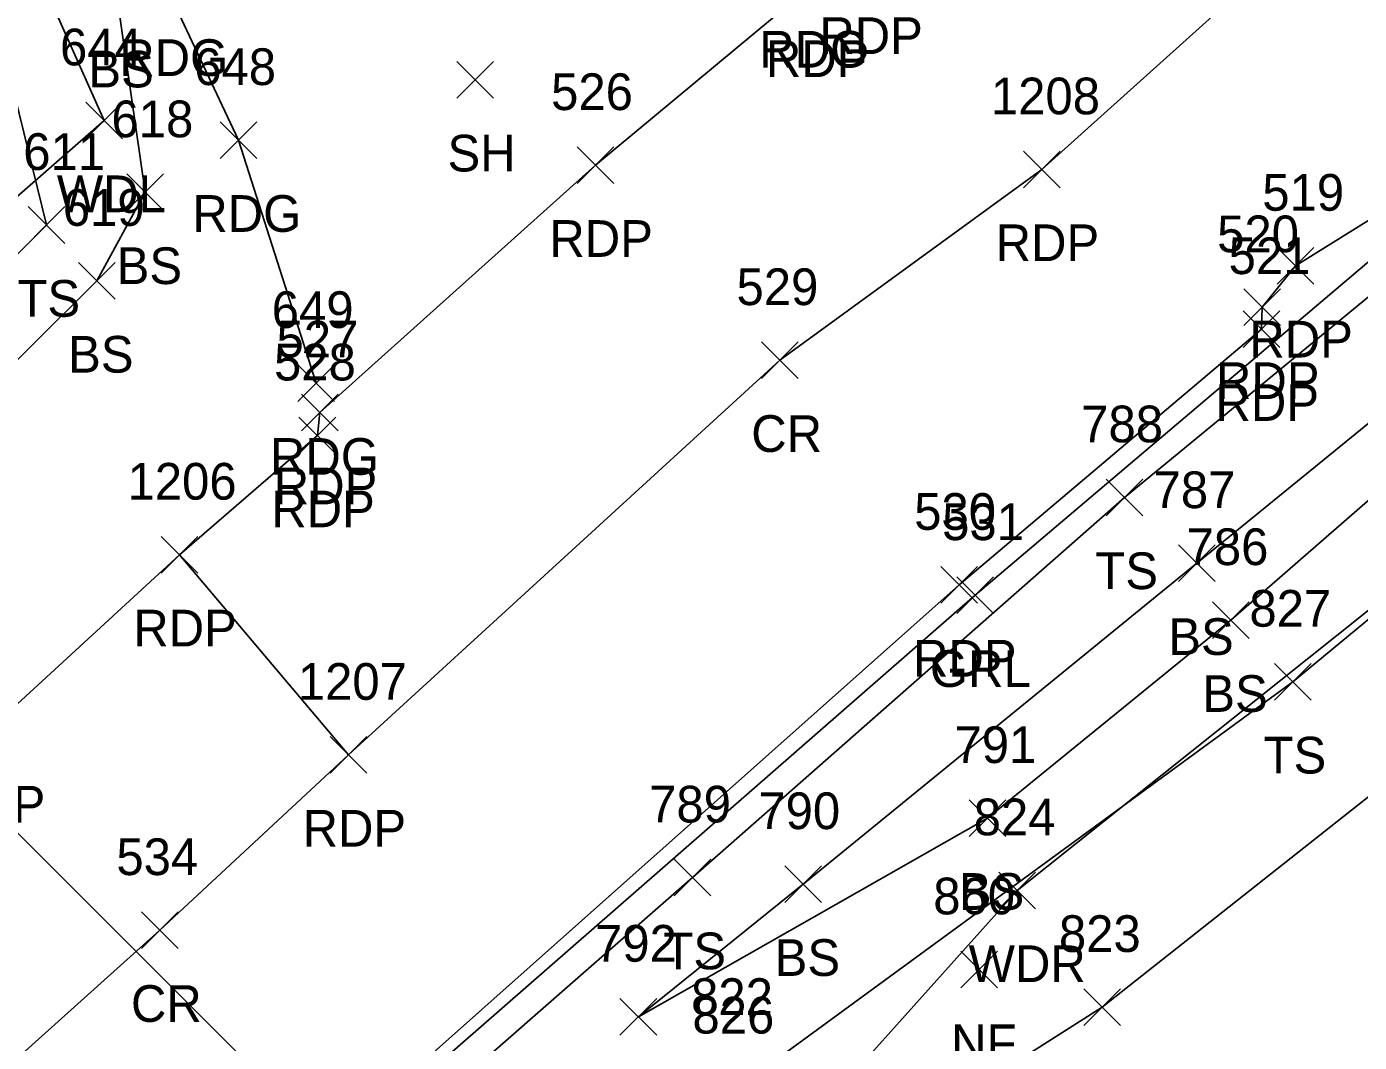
# Model space of a CAD drawing. Extents: x 1528286 to 1556263, y 492387 to 508952.
# Drawn here: x 1528468.6 to 1528541.2, y 492640.2 to 492695.5 of the extents above; entities that cross this region are included whole.
import ezdxf

# ---------------------------------------------------------------- set-up
doc = ezdxf.new("R2010")
doc.units = 0
for name, color, linetype in [('DCP', 7, 'Continuous'), ('L_A', 7, 'Continuous'), ('L_I', 7, 'Continuous'), ('L_TIC', 7, 'Continuous'), ('LAWA', 7, 'Continuous'), ('LELB', 7, 'Continuous'), ('P_A', 7, 'Continuous'), ('P_I', 7, 'Continuous'), ('P_TIC', 7, 'Continuous'), ('PET', 7, 'Continuous'), ('PEU', 7, 'Continuous'), ('PRC', 7, 'Continuous'), ('R_A', 7, 'Continuous'), ('R_I', 7, 'Continuous'), ('R_TIC', 7, 'Continuous'), ('RGR', 7, 'Continuous')]:
    doc.layers.add(name, color=color, linetype=linetype)

msp = doc.modelspace()

# ---------------------------------------------------------------- linework, layer by layer
at = {"layer": 'DCP'}
msp.add_line((1528459.882, 492659.784), (1528492.296, 492627.438), dxfattribs=at)
at = {"layer": 'L_TIC'}
for points in [[(1528492.036, 492691.653), (1528494.036, 492693.653)], [(1528494.036, 492691.653), (1528492.036, 492693.653)], [(1528492.036, 492691.653), (1528494.036, 492693.653)], [(1528494.036, 492691.653), (1528492.036, 492693.653)], [(1528471.803, 492689.435), (1528473.803, 492691.435)], [(1528473.803, 492689.435), (1528471.803, 492691.435)], [(1528471.803, 492689.435), (1528473.803, 492691.435)], [(1528473.803, 492689.435), (1528471.803, 492691.435)], [(1528474.042, 492685.518), (1528476.042, 492687.518)], [(1528476.042, 492685.518), (1528474.042, 492687.518)], [(1528474.042, 492685.518), (1528476.042, 492687.518)], [(1528476.042, 492685.518), (1528474.042, 492687.518)], [(1528468.663, 492683.737), (1528470.663, 492685.737)], [(1528470.663, 492683.737), (1528468.663, 492685.737)], [(1528468.663, 492683.737), (1528470.663, 492685.737)], [(1528470.663, 492683.737), (1528468.663, 492685.737)], [(1528471.395, 492680.69), (1528473.395, 492682.69)], [(1528473.395, 492680.69), (1528471.395, 492682.69)], [(1528471.395, 492680.69), (1528473.395, 492682.69)], [(1528473.395, 492680.69), (1528471.395, 492682.69)], [(1528527.44, 492668.894), (1528529.44, 492670.894)], [(1528529.44, 492668.894), (1528527.44, 492670.894)], [(1528527.44, 492668.894), (1528529.44, 492670.894)], [(1528529.44, 492668.894), (1528527.44, 492670.894)], [(1528531.387, 492665.306), (1528533.387, 492667.306)], [(1528533.387, 492665.306), (1528531.387, 492667.306)], [(1528531.387, 492665.306), (1528533.387, 492667.306)], [(1528533.387, 492665.306), (1528531.387, 492667.306)], [(1528533.242, 492662.203), (1528535.242, 492664.203)], [(1528535.242, 492662.203), (1528533.242, 492664.203)], [(1528533.242, 492662.203), (1528535.242, 492664.203)], [(1528535.242, 492662.203), (1528533.242, 492664.203)], [(1528536.612, 492658.846), (1528538.612, 492660.846)], [(1528538.612, 492658.846), (1528536.612, 492660.846)], [(1528536.612, 492658.846), (1528538.612, 492660.846)], [(1528538.612, 492658.846), (1528536.612, 492660.846)], [(1528519.965, 492651.416), (1528521.965, 492653.416)], [(1528521.965, 492651.416), (1528519.965, 492653.416)], [(1528519.965, 492651.416), (1528521.965, 492653.416)], [(1528521.965, 492651.416), (1528519.965, 492653.416)], [(1528503.886, 492648.176), (1528505.886, 492650.176)], [(1528505.886, 492648.176), (1528503.886, 492650.176)], [(1528503.886, 492648.176), (1528505.886, 492650.176)], [(1528505.886, 492648.176), (1528503.886, 492650.176)], [(1528509.922, 492647.814), (1528511.922, 492649.814)], [(1528511.922, 492647.814), (1528509.922, 492649.814)], [(1528509.922, 492647.814), (1528511.922, 492649.814)], [(1528511.922, 492647.814), (1528509.922, 492649.814)], [(1528521.579, 492647.478), (1528523.579, 492649.478)], [(1528523.579, 492647.478), (1528521.579, 492649.478)], [(1528521.579, 492647.478), (1528523.579, 492649.478)], [(1528523.579, 492647.478), (1528521.579, 492649.478)], [(1528519.506, 492643.17), (1528521.506, 492645.17)], [(1528521.506, 492643.17), (1528519.506, 492645.17)], [(1528519.506, 492643.17), (1528521.506, 492645.17)], [(1528521.506, 492643.17), (1528519.506, 492645.17)], [(1528526.225, 492641.12), (1528528.225, 492643.12)], [(1528528.225, 492641.12), (1528526.225, 492643.12)], [(1528526.225, 492641.12), (1528528.225, 492643.12)], [(1528528.225, 492641.12), (1528526.225, 492643.12)], [(1528500.929, 492640.591), (1528502.929, 492642.591)], [(1528502.929, 492640.591), (1528500.929, 492642.591)], [(1528500.929, 492640.591), (1528502.929, 492642.591)], [(1528502.929, 492640.591), (1528500.929, 492642.591)], [(1528500.929, 492640.591), (1528502.929, 492642.591)], [(1528502.929, 492640.591), (1528500.929, 492642.591)], [(1528500.929, 492640.591), (1528502.929, 492642.591)], [(1528502.929, 492640.591), (1528500.929, 492642.591)]]:
    msp.add_lwpolyline(points, dxfattribs=at)
at = {"layer": 'LAWA'}
for points in [[(1528305.143, 492527.842), (1528342.933, 492565.336), (1528378.694, 492601.441), (1528416.012, 492639), (1528453.009, 492673.153), (1528472.803, 492690.435), (1528460.273, 492718.435)], [(1528305.143, 492527.842), (1528342.933, 492565.336), (1528378.694, 492601.441), (1528416.012, 492639), (1528453.009, 492673.153), (1528472.803, 492690.435), (1528460.273, 492718.435)], [(1528350.567, 492486.658), (1528374.131, 492513.994), (1528413.925, 492550.925), (1528435.091, 492569.848), (1528453.537, 492583.197), (1528487.048, 492613.162), (1528503.178, 492626.813), (1528522.579, 492648.478), (1528559.072, 492677.555), (1528579.271, 492695.125), (1528598.445, 492712.961), (1528609.007, 492715.026)], [(1528350.567, 492486.658), (1528374.131, 492513.994), (1528413.925, 492550.925), (1528435.091, 492569.848), (1528453.537, 492583.197), (1528487.048, 492613.162), (1528503.178, 492626.813), (1528522.579, 492648.478), (1528559.072, 492677.555), (1528579.271, 492695.125), (1528598.445, 492712.961), (1528609.007, 492715.026)]]:
    msp.add_lwpolyline(points, dxfattribs=at)
at = {"layer": 'LELB'}
for points in [[(1528627.535, 492747.197), (1528602.245, 492728.24), (1528590.919, 492720.18), (1528561.7, 492697.236), (1528528.44, 492669.894), (1528504.886, 492649.176), (1528486.55, 492633.133), (1528477.153, 492624.603), (1528462.188, 492611.303), (1528435.473, 492586.893), (1528420.499, 492573.078), (1528389.262, 492542.582), (1528363.671, 492517.292), (1528340.83, 492494.601)], [(1528627.535, 492747.197), (1528602.245, 492728.24), (1528590.919, 492720.18), (1528561.7, 492697.236), (1528528.44, 492669.894), (1528504.886, 492649.176), (1528486.55, 492633.133), (1528477.153, 492624.603), (1528462.188, 492611.303), (1528435.473, 492586.893), (1528420.499, 492573.078), (1528389.262, 492542.582), (1528363.671, 492517.292), (1528340.83, 492494.601)], [(1528608.223, 492722.999), (1528593.799, 492717.472), (1528565.837, 492693.535), (1528532.387, 492666.306), (1528510.922, 492648.814), (1528501.929, 492641.591)], [(1528608.223, 492722.999), (1528593.799, 492717.472), (1528565.837, 492693.535), (1528532.387, 492666.306), (1528510.922, 492648.814), (1528501.929, 492641.591)], [(1528608.107, 492719.723), (1528594.767, 492716.381), (1528567.241, 492691.922), (1528534.242, 492663.203), (1528520.965, 492652.416), (1528501.929, 492641.591)], [(1528608.107, 492719.723), (1528594.767, 492716.381), (1528567.241, 492691.922), (1528534.242, 492663.203), (1528520.965, 492652.416), (1528501.929, 492641.591)], [(1528463.974, 492716.24), (1528473.5, 492697.234), (1528475.042, 492686.518), (1528472.395, 492681.69), (1528457.302, 492666.687)], [(1528463.974, 492716.24), (1528473.5, 492697.234), (1528475.042, 492686.518), (1528472.395, 492681.69), (1528457.302, 492666.687)], [(1528495.396, 492632.327), (1528503.178, 492626.813), (1528527.225, 492642.12), (1528549.208, 492659.483), (1528567.953, 492673.117), (1528585.347, 492688.372), (1528604.063, 492705.044), (1528609.007, 492715.026)], [(1528495.396, 492632.327), (1528503.178, 492626.813), (1528527.225, 492642.12), (1528549.208, 492659.483), (1528567.953, 492673.117), (1528585.347, 492688.372), (1528604.063, 492705.044), (1528609.007, 492715.026)], [(1528507.297, 492637.674), (1528537.612, 492659.846), (1528559.072, 492677.555), (1528579.271, 492695.125), (1528598.445, 492712.961), (1528609.007, 492715.026)], [(1528507.297, 492637.674), (1528537.612, 492659.846), (1528559.072, 492677.555), (1528579.271, 492695.125), (1528598.445, 492712.961), (1528609.007, 492715.026)], [(1528439.397, 492683.965), (1528447.056, 492673.146), (1528454.655, 492669.581), (1528469.663, 492684.737), (1528465.938, 492699.853), (1528459.238, 492709.386)], [(1528439.397, 492683.965), (1528447.056, 492673.146), (1528454.655, 492669.581), (1528469.663, 492684.737), (1528465.938, 492699.853), (1528459.238, 492709.386)]]:
    msp.add_lwpolyline(points, dxfattribs=at)
at = {"layer": 'P_TIC'}
for points in [[(1528479.12, 492688.363), (1528481.12, 492690.363)], [(1528481.12, 492688.363), (1528479.12, 492690.363)], [(1528479.12, 492688.363), (1528481.12, 492690.363)], [(1528481.12, 492688.363), (1528479.12, 492690.363)], [(1528498.589, 492687), (1528500.589, 492689)], [(1528500.589, 492687), (1528498.589, 492689)], [(1528498.589, 492687), (1528500.589, 492689)], [(1528500.589, 492687), (1528498.589, 492689)], [(1528522.925, 492686.768), (1528524.925, 492688.768)], [(1528524.925, 492686.768), (1528522.925, 492688.768)], [(1528522.925, 492686.768), (1528524.925, 492688.768)], [(1528524.925, 492686.768), (1528522.925, 492688.768)], [(1528536.757, 492681.515), (1528538.757, 492683.515)], [(1528538.757, 492681.515), (1528536.757, 492683.515)], [(1528536.757, 492681.515), (1528538.757, 492683.515)], [(1528538.757, 492681.515), (1528536.757, 492683.515)], [(1528534.94, 492679.254), (1528536.94, 492681.254)], [(1528536.94, 492679.254), (1528534.94, 492681.254)], [(1528534.94, 492679.254), (1528536.94, 492681.254)], [(1528536.94, 492679.254), (1528534.94, 492681.254)], [(1528534.911, 492678.061), (1528536.911, 492680.061)], [(1528536.911, 492678.061), (1528534.911, 492680.061)], [(1528534.911, 492678.061), (1528536.911, 492680.061)], [(1528536.911, 492678.061), (1528534.911, 492680.061)], [(1528508.653, 492676.371), (1528510.653, 492678.371)], [(1528510.653, 492676.371), (1528508.653, 492678.371)], [(1528508.653, 492676.371), (1528510.653, 492678.371)], [(1528510.653, 492676.371), (1528508.653, 492678.371)], [(1528483.355, 492675.123), (1528485.355, 492677.123)], [(1528485.355, 492675.123), (1528483.355, 492677.123)], [(1528483.355, 492675.123), (1528485.355, 492677.123)], [(1528485.355, 492675.123), (1528483.355, 492677.123)], [(1528483.561, 492673.516), (1528485.561, 492675.516)], [(1528485.561, 492673.516), (1528483.561, 492675.516)], [(1528483.561, 492673.516), (1528485.561, 492675.516)], [(1528485.561, 492673.516), (1528483.561, 492675.516)], [(1528483.425, 492672.265), (1528485.425, 492674.265)], [(1528485.425, 492672.265), (1528483.425, 492674.265)], [(1528483.425, 492672.265), (1528485.425, 492674.265)], [(1528485.425, 492672.265), (1528483.425, 492674.265)], [(1528475.901, 492665.769), (1528477.901, 492667.769)], [(1528477.901, 492665.769), (1528475.901, 492667.769)], [(1528475.901, 492665.769), (1528477.901, 492667.769)], [(1528477.901, 492665.769), (1528475.901, 492667.769)], [(1528518.42, 492664.123), (1528520.42, 492666.123)], [(1528520.42, 492664.123), (1528518.42, 492666.123)], [(1528518.42, 492664.123), (1528520.42, 492666.123)], [(1528520.42, 492664.123), (1528518.42, 492666.123)], [(1528485.131, 492654.861), (1528487.131, 492656.861)], [(1528487.131, 492654.861), (1528485.131, 492656.861)], [(1528485.131, 492654.861), (1528487.131, 492656.861)], [(1528487.131, 492654.861), (1528485.131, 492656.861)], [(1528474.829, 492645.31), (1528476.829, 492647.31)], [(1528476.829, 492645.31), (1528474.829, 492647.31)], [(1528474.829, 492645.31), (1528476.829, 492647.31)], [(1528476.829, 492645.31), (1528474.829, 492647.31)]]:
    msp.add_lwpolyline(points, dxfattribs=at)
at = {"layer": 'PET'}
for points in [[(1528523.925, 492687.768), (1528545.219, 492706.888)], [(1528523.925, 492687.768), (1528545.219, 492706.888)], [(1528560.517, 492699.264), (1528557.469, 492699.118), (1528553.458, 492694.773), (1528549.097, 492692.715), (1528547.05, 492688.292), (1528537.757, 492682.515), (1528535.94, 492680.254), (1528535.911, 492679.061), (1528519.42, 492665.123), (1528485.647, 492635.106), (1528449.898, 492603.317), (1528443.292, 492597.221), (1528441.443, 492597.056), (1528433.939, 492590.577), (1528430.616, 492585.987), (1528412.089, 492568.516), (1528375.77, 492531.986), (1528339.078, 492496.271)], [(1528560.517, 492699.264), (1528557.469, 492699.118), (1528553.458, 492694.773), (1528549.097, 492692.715), (1528547.05, 492688.292), (1528537.757, 492682.515), (1528535.94, 492680.254), (1528535.911, 492679.061), (1528519.42, 492665.123), (1528485.647, 492635.106), (1528449.898, 492603.317), (1528443.292, 492597.221), (1528441.443, 492597.056), (1528433.939, 492590.577), (1528430.616, 492585.987), (1528412.089, 492568.516), (1528375.77, 492531.986), (1528339.078, 492496.271)], [(1528514.309, 492699.055), (1528511.395, 492697.801), (1528499.589, 492688), (1528484.561, 492674.516), (1528484.425, 492673.265)], [(1528514.309, 492699.055), (1528511.395, 492697.801), (1528499.589, 492688), (1528484.561, 492674.516), (1528484.425, 492673.265)], [(1528523.925, 492687.768), (1528509.653, 492677.371)], [(1528523.925, 492687.768), (1528509.653, 492677.371)], [(1528486.131, 492655.861), (1528509.653, 492677.371)], [(1528486.131, 492655.861), (1528509.653, 492677.371)], [(1528484.425, 492673.265), (1528476.901, 492666.769)], [(1528484.425, 492673.265), (1528476.901, 492666.769)], [(1528466.456, 492657.166), (1528476.901, 492666.769)], [(1528466.456, 492657.166), (1528476.901, 492666.769)], [(1528476.901, 492666.769), (1528486.131, 492655.861)], [(1528476.901, 492666.769), (1528486.131, 492655.861)]]:
    msp.add_lwpolyline(points, dxfattribs=at)
at = {"layer": 'PEU'}
msp.add_lwpolyline([(1528464.703, 492721.592), (1528476.134, 492697.856), (1528480.12, 492689.363), (1528484.355, 492676.123)], dxfattribs=at)
msp.add_lwpolyline([(1528464.703, 492721.592), (1528476.134, 492697.856), (1528480.12, 492689.363), (1528484.355, 492676.123)], dxfattribs=at)
at = {"layer": 'PRC'}
for points in [[(1528545.219, 492706.888), (1528523.925, 492687.768)], [(1528545.219, 492706.888), (1528523.925, 492687.768)], [(1528509.653, 492677.371), (1528523.925, 492687.768)], [(1528509.653, 492677.371), (1528523.925, 492687.768)], [(1528509.653, 492677.371), (1528486.131, 492655.861)], [(1528509.653, 492677.371), (1528486.131, 492655.861)], [(1528475.829, 492646.31), (1528486.131, 492655.861)], [(1528475.829, 492646.31), (1528486.131, 492655.861)], [(1528475.829, 492646.31), (1528439.483, 492613.677)], [(1528475.829, 492646.31), (1528439.483, 492613.677)]]:
    msp.add_lwpolyline(points, dxfattribs=at)
at = {"layer": 'R_TIC'}
for points in [[(1528519.288, 492663.562), (1528521.288, 492665.562)], [(1528521.288, 492663.562), (1528519.288, 492665.562)], [(1528519.288, 492663.562), (1528521.288, 492665.562)], [(1528521.288, 492663.562), (1528519.288, 492665.562)]]:
    msp.add_lwpolyline(points, dxfattribs=at)
at = {"layer": 'RGR'}
msp.add_lwpolyline([(1528631.557, 492751.518), (1528593.228, 492723.7), (1528555.254, 492694.171), (1528520.288, 492664.562), (1528486.051, 492634.677), (1528450.283, 492602.919), (1528412.918, 492568.153), (1528376.626, 492531.198), (1528339.769, 492495.46)], dxfattribs=at)
msp.add_lwpolyline([(1528631.557, 492751.518), (1528593.228, 492723.7), (1528555.254, 492694.171), (1528520.288, 492664.562), (1528486.051, 492634.677), (1528450.283, 492602.919), (1528412.918, 492568.153), (1528376.626, 492531.198), (1528339.769, 492495.46)], dxfattribs=at)

# ---------------------------------------------------------------- texts
at = {"layer": 'L_A'}
for s, p in [('BS', (1528471.941, 492692.234)), ('BS', (1528471.941, 492692.234)), ('SH', (1528491.524, 492687.653)), ('SH', (1528491.524, 492687.653)), ('WDL', (1528470.22, 492685.435)), ('WDL', (1528470.22, 492685.435)), ('BS', (1528473.483, 492681.518)), ('BS', (1528473.483, 492681.518)), ('TS', (1528468.073, 492679.737)), ('TS', (1528468.073, 492679.737)), ('BS', (1528470.836, 492676.69)), ('BS', (1528470.836, 492676.69)), ('TS', (1528526.849, 492664.894)), ('TS', (1528526.849, 492664.894)), ('BS', (1528530.828, 492661.306)), ('BS', (1528530.828, 492661.306)), ('BS', (1528532.683, 492658.203)), ('BS', (1528532.683, 492658.203)), ('TS', (1528536.022, 492654.846)), ('TS', (1528536.022, 492654.846)), ('BS', (1528519.406, 492647.416)), ('BS', (1528519.406, 492647.416)), ('TS', (1528503.295, 492644.176)), ('TS', (1528503.295, 492644.176)), ('BS', (1528509.363, 492643.814)), ('BS', (1528509.363, 492643.814)), ('WDR', (1528519.941, 492643.478)), ('WDR', (1528519.941, 492643.478)), ('NF', (1528518.986, 492639.17)), ('NF', (1528518.986, 492639.17))]:
    msp.add_text(s, height=2, dxfattribs=at).set_placement(p)
at = {"layer": 'L_I'}
for s, p in [('644', (1528470.393, 492693.435)), ('644', (1528470.393, 492693.435)), ('618', (1528473.2, 492689.518)), ('618', (1528473.2, 492689.518)), ('611', (1528468.388, 492687.737)), ('611', (1528468.388, 492687.737)), ('619', (1528470.545, 492684.69)), ('619', (1528470.545, 492684.69)), ('788', (1528526.078, 492672.894)), ('788', (1528526.078, 492672.894)), ('787', (1528530.025, 492669.306)), ('787', (1528530.025, 492669.306)), ('786', (1528531.824, 492666.203)), ('786', (1528531.824, 492666.203)), ('827', (1528535.25, 492662.846)), ('827', (1528535.25, 492662.846)), ('791', (1528519.17, 492655.416)), ('791', (1528519.17, 492655.416)), ('789', (1528502.516, 492652.176)), ('789', (1528502.516, 492652.176)), ('790', (1528508.473, 492651.814)), ('790', (1528508.473, 492651.814)), ('824', (1528520.217, 492651.478)), ('824', (1528520.217, 492651.478)), ('860', (1528518.01, 492647.17)), ('860', (1528518.01, 492647.17)), ('792', (1528499.567, 492644.591)), ('792', (1528499.567, 492644.591)), ('792', (1528499.567, 492644.591)), ('792', (1528499.567, 492644.591)), ('823', (1528524.863, 492645.12)), ('823', (1528524.863, 492645.12)), ('822', (1528504.804, 492641.686)), ('822', (1528504.804, 492641.686)), ('826', (1528504.879, 492640.674)), ('826', (1528504.879, 492640.674))]:
    msp.add_text(s, height=2, dxfattribs=at).set_placement(p)
at = {"layer": 'P_A'}
for s, p in [('RDP', (1528511.797, 492694.055)), ('RDP', (1528511.797, 492694.055)), ('RDG', (1528508.518, 492693.314)), ('RDG', (1528508.518, 492693.314)), ('RDG', (1528473.622, 492692.856)), ('RDG', (1528473.622, 492692.856)), ('RDP', (1528508.883, 492692.801)), ('RDP', (1528508.883, 492692.801)), ('RDG', (1528477.608, 492684.363)), ('RDG', (1528477.608, 492684.363)), ('RDP', (1528497.078, 492683)), ('RDP', (1528497.078, 492683)), ('RDP', (1528521.414, 492682.768)), ('RDP', (1528521.414, 492682.768)), ('RDP', (1528535.246, 492677.515)), ('RDP', (1528535.246, 492677.515)), ('RDP', (1528533.428, 492675.254)), ('RDP', (1528533.428, 492675.254)), ('RDP', (1528533.4, 492674.061)), ('RDP', (1528533.4, 492674.061)), ('CR', (1528508.086, 492672.371)), ('CR', (1528508.086, 492672.371)), ('RDG', (1528481.843, 492671.123)), ('RDG', (1528481.843, 492671.123)), ('RDP', (1528482.05, 492669.516)), ('RDP', (1528482.05, 492669.516)), ('RDP', (1528481.913, 492668.265)), ('RDP', (1528481.913, 492668.265)), ('RDP', (1528474.389, 492661.769)), ('RDP', (1528474.389, 492661.769)), ('RDP', (1528516.909, 492660.123)), ('RDP', (1528516.909, 492660.123)), ('RDP', (1528463.944, 492652.166)), ('RDP', (1528463.944, 492652.166)), ('RDP', (1528483.62, 492650.861)), ('RDP', (1528483.62, 492650.861)), ('CR', (1528474.262, 492641.31)), ('CR', (1528474.262, 492641.31))]:
    msp.add_text(s, height=2, dxfattribs=at).set_placement(p)
at = {"layer": 'P_I'}
for s, p in [('648', (1528477.711, 492692.363)), ('648', (1528477.711, 492692.363)), ('526', (1528497.172, 492691)), ('526', (1528497.172, 492691)), ('1208', (1528521.154, 492690.768)), ('1208', (1528521.154, 492690.768)), ('519', (1528535.954, 492685.515)), ('519', (1528535.954, 492685.515)), ('520', (1528533.491, 492683.254)), ('520', (1528533.491, 492683.254)), ('521', (1528534.116, 492682.061)), ('521', (1528534.116, 492682.061)), ('529', (1528507.283, 492680.371)), ('529', (1528507.283, 492680.371)), ('649', (1528481.938, 492679.123)), ('649', (1528481.938, 492679.123)), ('527', (1528482.199, 492677.516)), ('527', (1528482.199, 492677.516)), ('528', (1528482.063, 492676.265)), ('528', (1528482.063, 492676.265)), ('1206', (1528474.074, 492669.769)), ('1206', (1528474.074, 492669.769)), ('530', (1528516.972, 492668.123)), ('530', (1528516.972, 492668.123)), ('1207', (1528483.36, 492658.861)), ('1207', (1528483.36, 492658.861)), ('534', (1528473.467, 492649.31)), ('534', (1528473.467, 492649.31))]:
    msp.add_text(s, height=2, dxfattribs=at).set_placement(p)
at = {"layer": 'R_A'}
msp.add_text('GRL', height=2, dxfattribs=at).set_placement((1528517.831, 492659.562))
msp.add_text('GRL', height=2, dxfattribs=at).set_placement((1528517.831, 492659.562))
at = {"layer": 'R_I'}
msp.add_text('531', height=2, dxfattribs=at).set_placement((1528518.493, 492667.562))
msp.add_text('531', height=2, dxfattribs=at).set_placement((1528518.493, 492667.562))

doc.saveas('drawing.dxf')
